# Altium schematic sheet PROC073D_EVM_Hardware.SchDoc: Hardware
size 431 x 279 mm; Date: Not shown in title block; ApprovedBy: Not shown in title block; CheckedBy: Not shown in title block; Author: Not shown in title block; CompanyName: Not shown in title block; DrawnBy: Charles F. Oladimeji; Engineer: Not shown in title block; Organization: Not shown in title block; Address1: Not shown in title block; Address2: Not shown in title block; Address3: Not shown in title block; Address4: Not shown in title block; DocumentNumber: 13; Revision: Use project parameter SCH_Rev; SheetNumber: 13; SheetTotal: 13; PageSetup: Record=PageOptions¦CenterHorizontal=True¦CenterVertical=True¦PrintScale=1.00¦XCorrection=1.00¦YCorrection=1.00¦PrintKind=0¦BorderSize=5000000¦LeftOffset=0¦BottomOffset=0¦Orientation=2¦PaperLength=1000¦PaperWidth=1000¦Scale=100¦PaperSource=15¦PrintQuality=600¦MediaType=1¦DitherType=10¦PaperKind=Letter¦PrintScaleMode=1
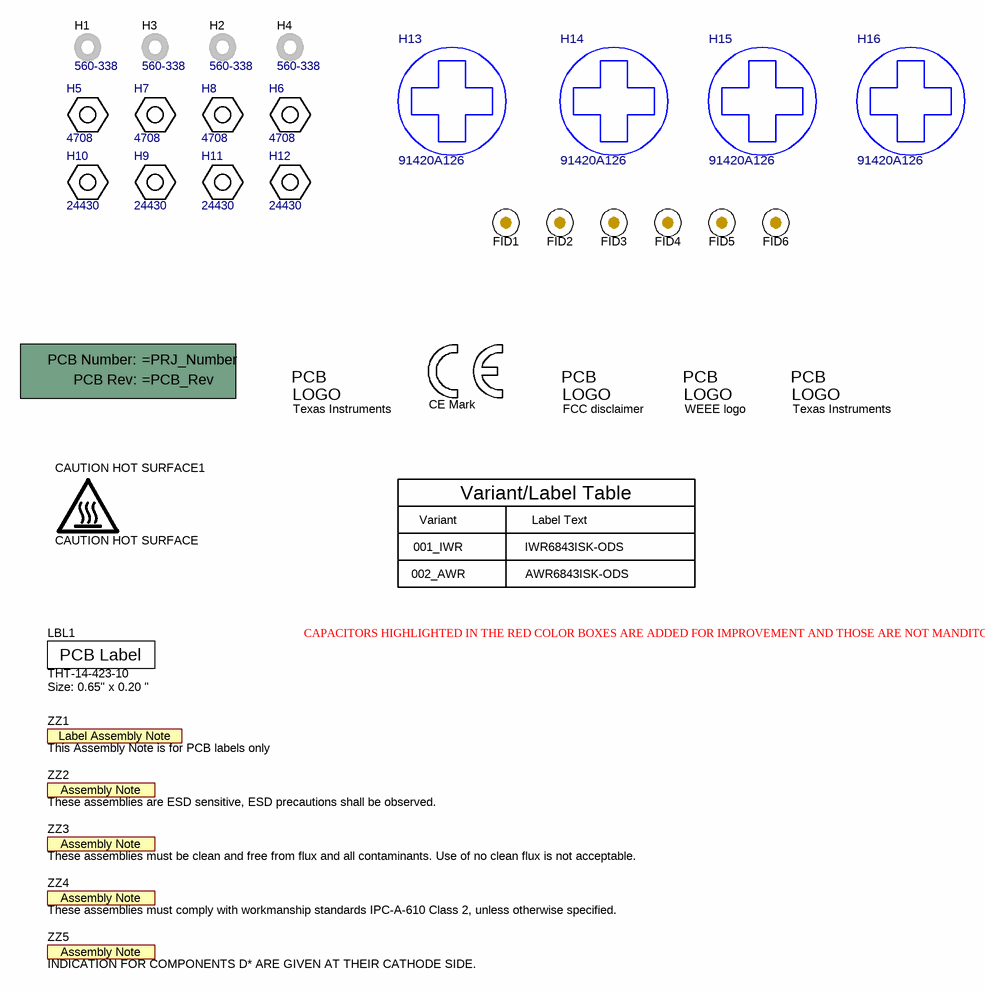
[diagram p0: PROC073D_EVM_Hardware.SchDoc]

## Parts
!PCB  Printed Circuit Board  (value not drawn)  (mechanical)
CAUTION_HOT_SURFACE1  CAUTION HOT SURFACE  [IEC_HotSurface_Small]  (no BOM)
FID1  Fiducial  [Fiducial10-20]  (value not drawn)
FID2  Fiducial  [Fiducial10-20]  (value not drawn)
FID3  Fiducial  [Fiducial10-20]  (value not drawn)
FID4  Fiducial  [Fiducial10-20]  (value not drawn)
FID5  Fiducial  [Fiducial10-20]  (value not drawn)
FID6  Fiducial  [Fiducial10-20]  (value not drawn)
H1  560-338  (mechanical)
H2  560-338  (mechanical)
H3  560-338  (mechanical)
H4  560-338  (mechanical)
H5  4708  (mechanical)
H6  4708  (mechanical)
H7  4708  (mechanical)
H8  4708  (mechanical)
H9  24430  (mechanical)
H10  24430  (mechanical)
H11  24430  (mechanical)
H12  24430  (mechanical)
H13  91420A126  [FP-91420A126_SCREW_M3X0.5-MFG]  (mechanical)
H14  91420A126  [FP-91420A126_SCREW_M3X0.5-MFG]  (mechanical)
H15  91420A126  [FP-91420A126_SCREW_M3X0.5-MFG]  (mechanical)
H16  91420A126  [FP-91420A126_SCREW_M3X0.5-MFG]  (mechanical)
LBL1  THT-14-423-10  Note: Size: 0.65" x 0.20 "  [Label_650x200]
Logo1  Texas Instruments  [TI_Stacked_Overlay_Small]  (no BOM)
Logo2  CE Mark  [CE_Mark_5mm]  (no BOM)
Logo3  FCC disclaimer  [FCC_disclaimer]  (no BOM)
Logo4  WEEE logo  [WEEE_Minimum]  (no BOM)
Logo5  Texas Instruments  [TI_Symbol_Overlay_Small]  (no BOM)
ZZ1  This Assembly Note is for PCB labels only  [AssemblyNoteLabel]  (no BOM)
ZZ2  These assemblies are ESD sensitive, ESD precautions shall be observed.  [AssemblyNote]  (no BOM)
ZZ3  These assemblies must be clean and free from flux and all contaminants. Use of no clean flux is not acceptable.  [AssemblyNote]  (no BOM)
ZZ4  These assemblies must comply with workmanship standards IPC-A-610 Class 2, unless otherwise specified.  [AssemblyNote]  (no BOM)
ZZ5  INDICATION FOR COMPONENTS D* ARE GIVEN AT THEIR CATHODE SIDE.  [AssemblyNote]  (no BOM)

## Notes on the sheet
- Variant
- 001_IWR
- Variant/Label Table
- Label Text
- IWR6843ISK-ODS
- 002_AWR
- AWR6843ISK-ODS
- CAPACITORS HIGHLIGHTED IN THE RED COLOR BOXES ARE ADDED FOR IMPROVEMENT AND THOSE ARE NOT MANDITORY.

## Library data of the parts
!PCB = CMP-0003618-2: Manufacturer: Any
CAUTION_HOT_SURFACE1 = CMP-0074837-1: IEC 61010-1 Hot Surface Warning; Library Reference: IEC_HotSurface; SymbolCreator: a0412235
FID1-FID6 = CMP-0077181-1: Fiducial mark.  There is nothing to buy or mount.
H1-H4 = CMP-0084015-1: Steel Plain Washer; Manufacturer: RS Pro
H5-H8 = CMP-0003742-1: HEX NUT 0.217" STEEL M3; Manufacturer: Keystone; CompType: Standoff
H9-H12 = CMP-0003759-1: HEX Standoff M3 Aluminum 5 MM; Manufacturer: Keystone
H13-H16 = CMP-0086605-1: Steel Phillips Flat Head Screws M3 x 0.5 mm Thread, 16 mm Long; Manufacturer: McMaster-Carr
LBL1 = CMP-0003625-1: Thermal Transfer Printable Labels, 0.650" W x 0.200" H - 10,000 per roll; Manufacturer: Brady; CompType: Label
Logo1 = CMP-0074838-1: Texas Instrument Corporate Signature; SymbolCreator: a0412235; Lib Reference: TI_Logo; Library Reference: Logo
Logo2 = CMP-0074844-1: SymbolCreator: a0412235
Logo3 = CMP-0074847-1: FCC_disclaimer; Library Reference: Logo
Logo4 = CMP-0074769-1
Logo5 = CMP-0074838-1: Texas Instrument Corporate Signature; Library Reference: Logo; SymbolCreator: a0412235; Lib Reference: TI_Logo
ZZ1 = CMP-0003616-3
ZZ2 = CMP-0077236-1
ZZ3 = CMP-0077237-1
ZZ4 ZZ5 = CMP-0077238-1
